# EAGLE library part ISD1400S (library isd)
VOICE PLAYBACK DEVICE
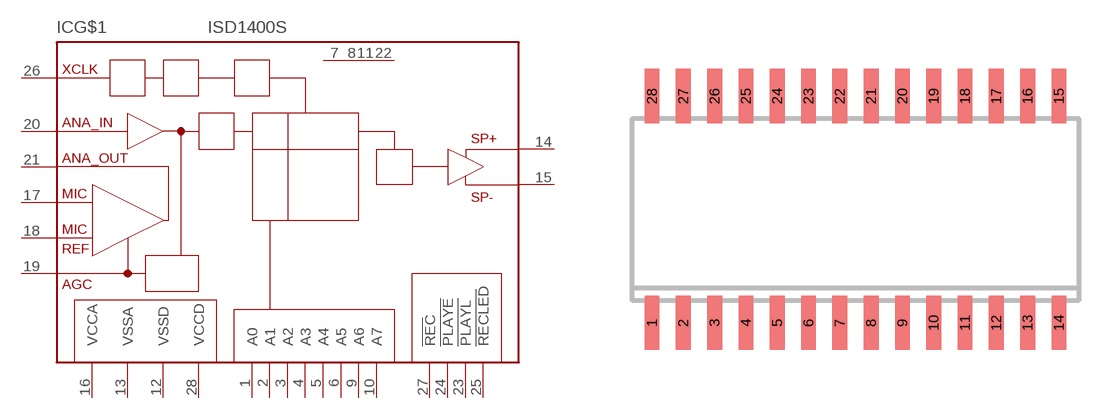
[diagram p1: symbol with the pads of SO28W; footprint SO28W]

Designator prefix IC; gates G$1=ISD1400 G$2=NC G$3=NC G$4=NC G$5=NC

## ISD1400S (OC_FARNELL: unknown; OC_NEWARK: unknown)  [SO28W]
1  G$1:A0  out
2  G$1:A1  out
3  G$1:A2  out
4  G$1:A3  out
5  G$1:A4  out
6  G$1:A5  out
7  G$2:NC  nc
8  G$3:NC  nc
9  G$1:A6  out
10  G$1:A7  out
11  G$4:NC  nc
12  G$1:VSSD  pwr
13  G$1:VSSA  pwr
14  G$1:SP+  out
15  G$1:SP-  out
16  G$1:VCCA  pwr
17  G$1:MIC  in
18  G$1:MIC_REF  in
19  G$1:AGC  pas
20  G$1:ANA_IN  in
21  G$1:ANA_OUT  out
22  G$5:NC  nc
23  G$1:PLAYL  in
24  G$1:PLAYE  in
25  G$1:RECLED  out
26  G$1:XCLK  in
27  G$1:REC  in
28  G$1:VCCD  pwr

## Footprint SO28W (pad centres in mm)
Wide Small Outline Package JEDEC MO-119 AB IPC SO28W
smd 0.6 x 2.2: 1 -8.255,-4.6; 2 -6.985,-4.6; 3 -5.715,-4.6; 4 -4.445,-4.6; 5 -3.175,-4.6; 6 -1.905,-4.6; 7 -0.635,-4.6; 8 0.635,-4.6; 9 1.905,-4.6; 10 3.175,-4.6; 11 4.445,-4.6; 12 5.715,-4.6; 13 6.985,-4.6; 14 8.255,-4.6; 15 8.255,4.6; 16 6.985,4.6; 17 5.715,4.6; 18 4.445,4.6; 19 3.175,4.6; 20 1.905,4.6; 21 0.635,4.6; 22 -0.635,4.6; 23 -1.905,4.6; 24 -3.175,4.6; 25 -4.445,4.6; 26 -5.715,4.6; 27 -6.985,4.6; 28 -8.255,4.6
